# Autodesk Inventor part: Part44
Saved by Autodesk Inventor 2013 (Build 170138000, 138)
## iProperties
Created: 2012-07
Part Number: Part44
Material: Generic
Document SubType Name: Modeling
Designer: Paul
Density: 1 g/cm^3
Author: Paul
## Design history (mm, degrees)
node "User Library-Arduino Mega.SAT1"
body "Solid1"
node "Base1"
